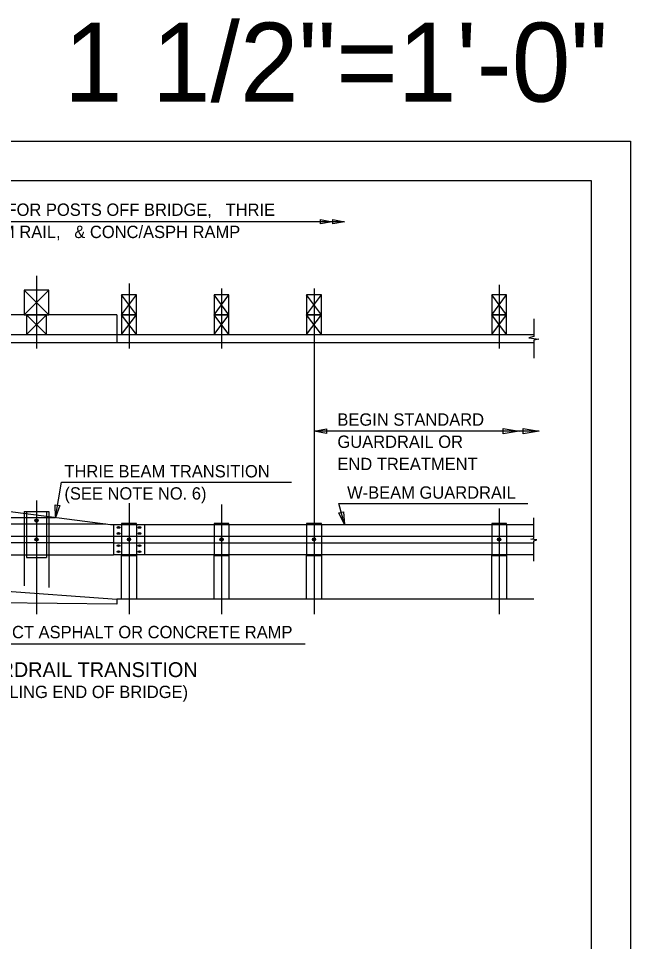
# Model space of a CAD drawing. Extents: x 0 to 22.7, y 0 to 15.7.
# Drawn here: x 17.5 to 22.67, y 7.91 to 15.7 of the extents above; entities that cross this region are included whole.
import ezdxf

# ---------------------------------------------------------------- set-up
doc = ezdxf.new("R2010")
doc.units = 0
for name, color, linetype in [('BORDER_ANNO_Cutsheet', 7, 'Continuous'), ('BRDG_ANNO_Anno-Sheet', 7, 'Continuous'), ('BRDG_ANNO_General-Notes', 7, 'Continuous'), ('BRDG_BASE_Dtlctrln', 7, 'Continuous'), ('BRDG_BASE_Phtline', 7, 'Continuous')]:
    doc.layers.add(name, color=color, linetype=linetype)

msp = doc.modelspace()

# ---------------------------------------------------------------- linework, layer by layer
at = {"layer": 'BORDER_ANNO_Cutsheet'}
msp.add_lwpolyline([(0, 14.6667), (22.6667, 14.6667), (22.6667, 0), (0, 0)], close=True, dxfattribs=at)
at = {"layer": 'BRDG_ANNO_Anno-Sheet'}
msp.add_lwpolyline([(1, 14.3333), (22.3333, 14.3333), (22.3333, 0.3333), (1, 0.3333)], close=True, dxfattribs=at)
at = {"layer": 'BRDG_ANNO_General-Notes'}
for p, q in [((20.252, 13.9864), (14.4561, 13.9864)), ((20.0479, 13.9677), (20.0479, 14.0052)), ((20.0479, 14.0052), (20.1479, 13.9864)), ((20.1479, 13.9864), (20.0479, 13.9677)), ((20.152, 13.9677), (20.152, 14.0052)), ((20.152, 14.0052), (20.252, 13.9864)), ((20.252, 13.9864), (20.152, 13.9677)), ((19.994, 12.2181), (20.099, 12.2378)), ((20.099, 12.2378), (20.099, 12.1984)), ((21.8945, 12.2181), (19.994, 12.2181)), ((20.099, 12.1984), (19.994, 12.2181)), ((17.8086, 11.5971), (17.8474, 11.5906)), ((17.8107, 11.4903), (17.8086, 11.5971)), ((17.8474, 11.5906), (17.8107, 11.4903)), ((20.2045, 11.5271), (20.2426, 11.5369)), ((20.2426, 11.5369), (20.2498, 11.4303)), ((20.2498, 11.4303), (20.2045, 11.5271)), ((16.7052, 10.4213), (19.9203, 10.4213))]:
    msp.add_line(p, q, dxfattribs=at)
for points in [[(21.5915, 12.2402), (21.7248, 12.2181), (21.5915, 12.1961)], [(21.7611, 12.2402), (21.8945, 12.2181), (21.7611, 12.1961)]]:
    msp.add_lwpolyline(points, close=True, dxfattribs=at)
for points in [[(17.8107, 11.4903), (17.8602, 11.7862), (19.8026, 11.7862)], [(20.2039, 11.6081), (21.7996, 11.6081)], [(20.2498, 11.4303), (20.2039, 11.6081)]]:
    msp.add_lwpolyline(points, dxfattribs=at)
at = {"layer": 'BRDG_BASE_Dtlctrln'}
for p, q in [((17.6502, 13.5289), (17.6502, 12.9157)), ((18.4315, 13.464), (18.4315, 12.9157)), ((19.2127, 13.4211), (19.2127, 12.9157)), ((19.994, 13.4211), (19.994, 10.6736)), ((21.5565, 13.4545), (21.5565, 12.9157)), ((17.6502, 11.6319), (17.6502, 10.6736)), ((18.4315, 11.6089), (18.4315, 10.6736)), ((19.2127, 11.5986), (19.2127, 10.6736)), ((21.5565, 11.5645), (21.5565, 10.6736))]:
    msp.add_line(p, q, dxfattribs=at)
at = {"layer": 'BRDG_BASE_Phtline'}
for p, q in [((17.546, 13.2011), (17.7544, 13.4095)), ((17.7544, 13.2011), (17.546, 13.4095)), ((18.369, 13.2011), (18.494, 13.3678)), ((18.494, 13.2011), (18.369, 13.3678)), ((19.1502, 13.2011), (19.2752, 13.3678)), ((19.2752, 13.2011), (19.1502, 13.3678)), ((19.9315, 13.2011), (20.0565, 13.3678)), ((20.0565, 13.2011), (19.9315, 13.3678)), ((21.494, 13.2011), (21.619, 13.3678)), ((21.619, 13.2011), (21.494, 13.3678)), ((17.546, 13.2011), (16.9731, 13.2011)), ((17.5669, 13.0345), (17.7335, 13.2011)), ((17.7335, 13.0345), (17.5669, 13.2011)), ((18.3273, 13.2011), (17.7544, 13.2011)), ((18.3273, 13.2011), (18.3273, 13.0345)), ((18.369, 13.0345), (18.494, 13.2011)), ((18.494, 13.0345), (18.369, 13.2011)), ((19.1502, 13.0345), (19.2752, 13.2011)), ((19.2752, 13.0345), (19.1502, 13.2011)), ((19.9315, 13.0345), (20.0565, 13.2011)), ((20.0565, 13.0345), (19.9315, 13.2011)), ((21.494, 13.0345), (21.619, 13.2011)), ((21.619, 13.0345), (21.494, 13.2011)), ((16.7387, 13.0345), (21.8499, 13.0345)), ((18.3273, 13.0345), (18.3273, 12.9668)), ((16.7387, 12.9668), (21.8499, 12.9668)), ((17.0252, 11.5918), (18.2752, 11.4303)), ((17.546, 11.5388), (17.7544, 11.5388)), ((17.546, 11.5388), (17.546, 11.5245)), ((17.5669, 11.5388), (17.5669, 11.5218)), ((17.7335, 11.5388), (17.7335, 11.5003)), ((17.7544, 11.5388), (17.7544, 11.4976)), ((16.9992, 11.4904), (17.8105, 11.4904)), ((17.546, 11.5245), (17.546, 11.1751)), ((17.5669, 11.5218), (17.5669, 11.1751)), ((17.7335, 11.5003), (17.7335, 11.1751)), ((17.7544, 11.4976), (17.7544, 11.1751)), ((16.9992, 11.4354), (18.2359, 11.4354)), ((18.2752, 11.4303), (21.8499, 11.4303)), ((18.3012, 11.4303), (18.3012, 11.1751)), ((18.369, 11.4303), (18.369, 11.1751)), ((18.494, 11.4303), (18.494, 11.1751)), ((18.5617, 11.4303), (18.5617, 11.1751)), ((19.1502, 11.4303), (19.1502, 11.1751)), ((19.2752, 11.4303), (19.2752, 11.1751)), ((19.9315, 11.4303), (19.9315, 11.1751)), ((20.0565, 11.4303), (20.0565, 11.1751)), ((21.494, 11.4303), (21.494, 11.1751)), ((21.619, 11.4303), (21.619, 11.1751)), ((16.9992, 11.3315), (18.3012, 11.3315)), ((18.3012, 11.3302), (21.8499, 11.3302)), ((16.9992, 11.2766), (18.3012, 11.2766)), ((18.3012, 11.2753), (21.8499, 11.2753)), ((16.9992, 11.1751), (18.3012, 11.1751)), ((17.546, 11.1751), (17.546, 10.9115)), ((17.5669, 11.1751), (17.5669, 11.1504)), ((17.5669, 11.1504), (17.7335, 11.1504)), ((17.7335, 11.1751), (17.7335, 11.1504)), ((17.7544, 11.1751), (17.7544, 10.8967)), ((21.8499, 11.1751), (18.3012, 11.1751)), ((18.369, 10.8001), (18.369, 11.166)), ((18.494, 11.166), (18.494, 10.8001)), ((19.1502, 10.8001), (19.1502, 11.166)), ((19.2752, 11.166), (19.2752, 10.8001)), ((19.9315, 10.8001), (19.9315, 11.166)), ((20.0565, 11.166), (20.0565, 10.8001)), ((21.494, 10.8001), (21.494, 11.166)), ((21.619, 11.166), (21.619, 10.8001)), ((15.0244, 11.0356), (18.3273, 10.8001)), ((18.3273, 10.7584), (15.0244, 10.794)), ((21.8499, 10.8001), (18.3273, 10.8001)), ((18.3273, 10.8001), (18.3273, 10.7584))]:
    msp.add_line(p, q, dxfattribs=at)
for points in [[(17.546, 13.2011), (17.7544, 13.2011), (17.7544, 13.4095), (17.546, 13.4095)], [(18.369, 13.2011), (18.494, 13.2011), (18.494, 13.3678), (18.369, 13.3678)], [(19.1502, 13.2011), (19.2752, 13.2011), (19.2752, 13.3678), (19.1502, 13.3678)], [(19.9315, 13.2011), (20.0565, 13.2011), (20.0565, 13.3678), (19.9315, 13.3678)], [(21.494, 13.2011), (21.619, 13.2011), (21.619, 13.3678), (21.494, 13.3678)], [(17.5669, 13.0345), (17.7335, 13.0345), (17.7335, 13.2011), (17.5669, 13.2011)], [(18.369, 13.0345), (18.494, 13.0345), (18.494, 13.2011), (18.369, 13.2011)], [(19.1502, 13.0345), (19.2752, 13.0345), (19.2752, 13.2011), (19.1502, 13.2011)], [(19.9315, 13.0345), (20.0565, 13.0345), (20.0565, 13.2011), (19.9315, 13.2011)], [(21.494, 13.0345), (21.619, 13.0345), (21.619, 13.2011), (21.494, 13.2011)]]:
    msp.add_lwpolyline(points, close=True, dxfattribs=at)
for points in [[(21.8499, 13.1673), (21.8499, 13.0162), (21.8082, 13.0058), (21.8499, 13.0006), (21.8916, 12.9954), (21.8499, 12.985), (21.8499, 12.834)], [(21.8499, 11.1204), (21.8499, 11.293), (21.8759, 11.2995), (21.8499, 11.3027), (21.8239, 11.306), (21.8499, 11.3125), (21.8499, 11.485)], [(18.494, 11.4303), (18.494, 11.4394), (18.369, 11.4394), (18.369, 11.4303)], [(19.2752, 11.4303), (19.2752, 11.4394), (19.1502, 11.4394), (19.1502, 11.4303)], [(20.0565, 11.4303), (20.0565, 11.4394), (19.9315, 11.4394), (19.9315, 11.4303)], [(21.619, 11.4303), (21.619, 11.4394), (21.494, 11.4394), (21.494, 11.4303)], [(18.494, 11.1751), (18.494, 11.166), (18.369, 11.166), (18.369, 11.1751)], [(19.2752, 11.1751), (19.2752, 11.166), (19.1502, 11.166), (19.1502, 11.1751)], [(20.0565, 11.1751), (20.0565, 11.166), (19.9315, 11.166), (19.9315, 11.1751)], [(21.619, 11.1751), (21.619, 11.166), (21.494, 11.166), (21.494, 11.1751)]]:
    msp.add_lwpolyline(points, dxfattribs=at)
for centre, radius in [((17.6502, 11.4629), 0.0137), ((17.6502, 11.4629), 0.00651), ((17.6502, 11.304), 0.0137), ((17.6502, 11.304), 0.00651), ((18.4314, 11.304), 0.0137), ((18.4314, 11.304), 0.00651), ((19.2127, 11.304), 0.0137), ((19.2127, 11.304), 0.00651), ((19.9939, 11.304), 0.0137), ((19.9939, 11.304), 0.00651), ((21.5564, 11.304), 0.0137), ((21.5564, 11.304), 0.00651)]:
    msp.add_circle(centre, radius, dxfattribs=at)
for centre, major_axis, ratio in [((17.6502, 11.4629), (0, 0.00977), 0.666667), ((18.3429, 11.405), (0.0137, 0), 0.5), ((18.3429, 11.405), (0.00651, 0), 0.75), ((18.3429, 11.405), (0.00651, 0), 0.5), ((18.52, 11.405), (0.0137, 0), 0.5), ((18.52, 11.405), (0.00651, 0), 0.75), ((18.52, 11.405), (0.00651, 0), 0.5), ((17.6502, 11.304), (0, 0.00977), 0.666667), ((18.3429, 11.3542), (0.0137, 0), 0.5), ((18.3429, 11.3542), (0.00651, 0), 0.75), ((18.3429, 11.3542), (0.00651, 0), 0.5), ((18.4314, 11.304), (0, 0.00977), 0.666667), ((18.52, 11.3542), (0.0137, 0), 0.5), ((18.52, 11.3542), (0.00651, 0), 0.75), ((18.52, 11.3542), (0.00651, 0), 0.5), ((19.2127, 11.304), (0, 0.00977), 0.666667), ((19.9939, 11.304), (0, 0.00977), 0.666667), ((21.5564, 11.304), (0, 0.00977), 0.666667), ((18.3429, 11.2512), (0.0137, 0), 0.5), ((18.3429, 11.2512), (-0.00651, 0), 0.75), ((18.3429, 11.2512), (0.00651, 0), 0.5), ((18.52, 11.2512), (0.0137, 0), 0.5), ((18.52, 11.2512), (-0.00651, 0), 0.75), ((18.52, 11.2512), (0.00651, 0), 0.5), ((18.3429, 11.2005), (0.0137, 0), 0.5), ((18.3429, 11.2005), (-0.00651, 0), 0.75), ((18.3429, 11.2005), (0.00651, 0), 0.5), ((18.52, 11.2005), (0.0137, 0), 0.5), ((18.52, 11.2005), (-0.00651, 0), 0.75), ((18.52, 11.2005), (0.00651, 0), 0.5)]:
    msp.add_ellipse(centre, major_axis=major_axis, ratio=ratio, dxfattribs=at)

# ---------------------------------------------------------------- texts
at = {"layer": 'BRDG_ANNO_Anno-Sheet'}
msp.add_text('1 1/2"=1\'-0"', height=0.666667, dxfattribs=at).set_placement((17.8808, 15))
at = {"layer": 'BRDG_ANNO_General-Notes'}
for s, height, p in [('ROADWAY PAY ITEM LIMITS FOR POSTS OFF BRIDGE,   THRIE', 0.104167, (15.4621, 14.0357)), ('BEAM TRANSITION,   W-BEAM RAIL,   & CONC/ASPH RAMP', 0.104167, (15.4621, 13.8482)), ('BEGIN STANDARD ', 0.104167, (20.1913, 12.264)), ('GUARDRAIL OR ', 0.104167, (20.1913, 12.0765)), ('THRIE BEAM TRANSITION', 0.104167, (17.886, 11.8276)), ('END TREATMENT', 0.104167, (20.1913, 11.889)), ('(SEE NOTE NO. 6)', 0.104167, (17.886, 11.6401)), ('W-BEAM GUARDRAIL', 0.104167, (20.2731, 11.6477)), ('CONSTRUCT ASPHALT OR CONCRETE RAMP', 0.104167, (16.7546, 10.4696)), ('THRIE BEAM TO W-BEAM GUARDRAIL TRANSITION', 0.125, (14.8963, 10.1419)), ('(TYPICAL FOR APPROACH AND TRAILING END OF BRIDGE)', 0.104167, (14.9517, 9.9648))]:
    msp.add_text(s, height=height, dxfattribs=at).set_placement(p)

doc.saveas('drawing.dxf')
